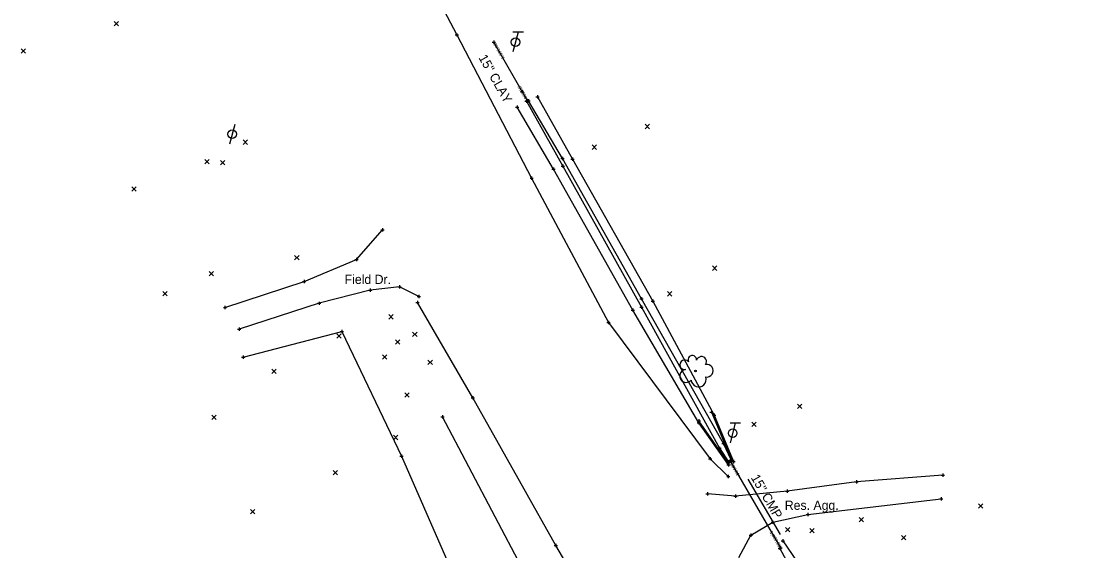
# Model space of a CAD drawing. Extents: x 2298098 to 2302860, y 557788 to 564251.
# Drawn here: x 2299909.5 to 2300233.1, y 560543.3 to 560704.7 of the extents above; entities that cross this region are included whole.
import ezdxf

# ---------------------------------------------------------------- set-up
doc = ezdxf.new("R2010")
doc.units = 0
for name, color, linetype in [('DR_X_Ditch', 7, 'Continuous'), ('DR_X_Elev_Flow', 7, 'Continuous'), ('DR_X_Storm_Sewer', 7, 'Continuous'), ('DR_X_Text', 7, 'Continuous'), ('PV_X_Curb', 7, 'Continuous'), ('PV_X_Driveway', 7, 'Continuous'), ('PV_X_Text', 7, 'Continuous'), ('SC_Scratch1', 7, 'Continuous'), ('SV_X_Break_Lines', 7, 'Continuous'), ('SV_X_Random_Point', 7, 'Continuous'), ('SV_X_Shot_Marker', 7, 'Continuous'), ('UT_X_Telecom_Cells', 7, 'Continuous'), ('UT_X_Unknown_Cells', 7, 'Continuous'), ('VG_X_Cells', 7, 'Continuous')]:
    doc.layers.add(name, color=color, linetype=linetype)

msp = doc.modelspace()

# ---------------------------------------------------------------- linework, layer by layer
at = {"layer": 'DR_X_Ditch'}
for points in [[(2300063.52, 560680.3), (2300074.62, 560660.51), (2300098.62, 560617.55), (2300122.4, 560574.49), (2300125.1, 560570.36)], [(2300125.91, 560570.98), (2300123.6, 560575.94), (2300098.62, 560620.12), (2300074.45, 560662.9), (2300064.1, 560680.42)], [(2300140.73, 560543.99), (2300148.01, 560530.6), (2300173.36, 560487.93), (2300199.8, 560447.46)]]:
    msp.add_lwpolyline(points, dxfattribs=at)
at = {"layer": 'DR_X_Elev_Flow'}
for p, q in [((2300053.09, 560698.3), (2300054.09, 560698.3)), ((2300053.59, 560698.8), (2300053.59, 560697.8)), ((2300053.59, 560698.3), (2300053.59, 560698.3)), ((2300063.29, 560680.42), (2300064.29, 560680.42)), ((2300063.79, 560680.92), (2300063.79, 560679.92)), ((2300063.79, 560680.42), (2300063.79, 560680.42)), ((2300125.63, 560571.09), (2300125.63, 560570.09)), ((2300125.13, 560570.59), (2300126.13, 560570.59)), ((2300125.63, 560570.59), (2300125.63, 560570.59)), ((2300140.45, 560544.14), (2300141.45, 560544.14)), ((2300140.95, 560544.64), (2300140.95, 560543.64)), ((2300140.95, 560544.14), (2300140.95, 560544.14))]:
    msp.add_line(p, q, dxfattribs=at)
at = {"layer": 'DR_X_Storm_Sewer'}
for p, q in [((2300063.79, 560680.42), (2300053.59, 560698.3)), ((2300125.63, 560570.59), (2300140.95, 560544.14))]:
    msp.add_line(p, q, dxfattribs=at)
at = {"layer": 'DR_X_Text'}
msp.add_line((2300140.93, 560548.2), (2300131.15, 560565.1), dxfattribs=at)
at = {"layer": 'PV_X_Curb'}
for points in [[(2300066.91, 560681.69), (2300077.5, 560662.65), (2300102.02, 560619.33), (2300120.74, 560584.58), (2300126.65, 560570.43)], [(2300125.1, 560569.46), (2300116.03, 560582.25), (2300095.96, 560616.58), (2300071.76, 560659.65), (2300060.65, 560678.51)], [(2300119.92, 560585.56), (2300126.1, 560570.69)], [(2300124.98, 560570.09), (2300116.05, 560582.88)], [(2300141.66, 560546.3), (2300150.4, 560533.52), (2300175.79, 560490.38), (2300201.81, 560451.09), (2300229.19, 560414.22)]]:
    msp.add_lwpolyline(points, dxfattribs=at)
at = {"layer": 'PV_X_Driveway'}
for points in [[(2299971.58, 560617.42), (2299995.74, 560625.32), (2300011.7, 560632.08), (2300019.59, 560641.14)], [(2300030.65, 560620.78), (2300024.79, 560623.76), (2300015.85, 560622.74), (2300000.3, 560618.7), (2299975.89, 560610.83)], [(2300190.42, 560566.32), (2300164.1, 560564.3), (2300143.01, 560561.46), (2300127.24, 560559.9), (2300118.69, 560560.61)], [(2300128.29, 560541.17), (2300131.9, 560547.98), (2300138.66, 560551.93), (2300149.28, 560554.27), (2300189.99, 560559.13)]]:
    msp.add_lwpolyline(points, dxfattribs=at)
at = {"layer": 'SV_X_Break_Lines'}
for points in [[(2299980.36, 560823), (2299996.31, 560788.88), (2300018.92, 560744.96), (2300042.25, 560700.52), (2300065.09, 560656.83), (2300088.55, 560612.83), (2300119.49, 560571.33), (2300125.05, 560565.91)], [(2300398.05, 560096.62), (2300363.97, 560133.96), (2300330.95, 560172.02), (2300298.04, 560211.71), (2300266.61, 560251.65), (2300236.37, 560291.53), (2300207.47, 560332.84), (2300178.37, 560374.68), (2300151.28, 560415.3), (2300123.6, 560459.08), (2300097.78, 560501.73), (2300072.42, 560544.84), (2300047.18, 560589.85), (2300030.27, 560619)], [(2299977.11, 560602.31), (2300007.25, 560610.14), (2300025.38, 560572.14), (2300045.56, 560526.04), (2300066.45, 560482.53), (2300086, 560434.38), (2300113.14, 560386.24), (2300137.98, 560345.34), (2300163.42, 560304.75), (2300191.32, 560264.85), (2300220.76, 560218.4), (2300248.98, 560175.76), (2300284.57, 560133.57), (2300319.56, 560088.68), (2300350.07, 560059.81)], [(2300381.27, 560083.36), (2300351.97, 560122.59), (2300319.35, 560161.59), (2300285.86, 560201.5), (2300253.42, 560241.93), (2300223.14, 560281.83), (2300192.99, 560321.43), (2300165.5, 560364.16), (2300137.47, 560403.52), (2300110, 560448.16), (2300084.4, 560491.86), (2300061.94, 560538.37), (2300037.88, 560584.07)]]:
    msp.add_lwpolyline(points, dxfattribs=at)
at = {"layer": 'SV_X_Random_Point'}
for p, q in [((2299937.78, 560703.34), (2299939.11, 560704.68)), ((2299937.78, 560704.68), (2299939.11, 560703.34)), ((2299909.45, 560694.96), (2299910.79, 560696.29)), ((2299909.45, 560696.29), (2299910.79, 560694.96)), ((2300099.67, 560671.95), (2300101.01, 560673.28)), ((2300099.67, 560673.28), (2300101.01, 560671.95)), ((2299977.1, 560667.17), (2299978.43, 560668.5)), ((2299977.1, 560668.5), (2299978.43, 560667.17)), ((2300083.51, 560665.65), (2300084.85, 560666.98)), ((2300083.51, 560666.98), (2300084.85, 560665.65)), ((2299965.46, 560661.22), (2299966.8, 560662.56)), ((2299965.46, 560662.56), (2299966.8, 560661.22)), ((2299970.23, 560660.91), (2299971.56, 560662.24)), ((2299970.23, 560662.24), (2299971.56, 560660.91)), ((2299943.13, 560652.89), (2299944.46, 560654.22)), ((2299943.13, 560654.22), (2299944.46, 560652.89)), ((2299992.82, 560631.96), (2299994.15, 560633.3)), ((2299992.82, 560633.3), (2299994.15, 560631.96)), ((2300120.21, 560628.75), (2300121.54, 560630.09)), ((2300120.21, 560630.09), (2300121.54, 560628.75)), ((2299966.72, 560627.07), (2299968.05, 560628.4)), ((2299966.72, 560628.4), (2299968.05, 560627.07)), ((2299952.61, 560621.01), (2299953.95, 560622.34)), ((2299952.61, 560622.34), (2299953.95, 560621.01)), ((2300106.47, 560620.93), (2300107.8, 560622.26)), ((2300106.47, 560622.26), (2300107.8, 560620.93)), ((2300021.53, 560613.92), (2300022.86, 560615.25)), ((2300021.53, 560615.25), (2300022.86, 560613.92)), ((2300028.8, 560608.6), (2300030.13, 560609.94)), ((2300028.8, 560609.94), (2300030.13, 560608.6)), ((2300005.64, 560608.06), (2300006.98, 560609.39)), ((2300005.64, 560609.39), (2300006.98, 560608.06)), ((2300023.54, 560606.25), (2300024.87, 560607.59)), ((2300023.54, 560607.59), (2300024.87, 560606.25)), ((2300019.57, 560601.7), (2300020.91, 560603.03)), ((2300019.57, 560603.03), (2300020.91, 560601.7)), ((2300033.47, 560600.04), (2300034.81, 560601.37)), ((2300033.47, 560601.37), (2300034.81, 560600.04)), ((2299985.88, 560597.32), (2299987.22, 560598.65)), ((2299985.88, 560598.65), (2299987.22, 560597.32)), ((2300026.44, 560590.12), (2300027.77, 560591.45)), ((2300026.44, 560591.45), (2300027.77, 560590.12)), ((2300146.15, 560586.65), (2300147.49, 560587.99)), ((2300146.15, 560587.99), (2300147.49, 560586.65)), ((2299967.59, 560583.24), (2299968.92, 560584.57)), ((2299967.59, 560584.57), (2299968.92, 560583.24)), ((2300132.19, 560581.14), (2300133.52, 560582.48)), ((2300132.19, 560582.48), (2300133.52, 560581.14)), ((2300022.99, 560577.11), (2300024.32, 560578.45)), ((2300022.99, 560578.45), (2300024.32, 560577.11)), ((2300004.52, 560566.42), (2300005.86, 560567.75)), ((2300004.52, 560567.75), (2300005.86, 560566.42)), ((2299979.39, 560554.47), (2299980.72, 560555.81)), ((2299979.39, 560555.81), (2299980.72, 560554.47)), ((2300201.29, 560556.26), (2300202.62, 560557.6)), ((2300201.29, 560557.6), (2300202.62, 560556.26)), ((2300164.94, 560552.08), (2300166.27, 560553.42)), ((2300164.94, 560553.42), (2300166.27, 560552.08)), ((2300142.48, 560549.05), (2300143.81, 560550.38)), ((2300142.48, 560550.38), (2300143.81, 560549.05)), ((2300149.92, 560548.73), (2300151.25, 560550.06)), ((2300149.92, 560550.06), (2300151.25, 560548.73)), ((2300177.81, 560546.62), (2300179.14, 560547.95)), ((2300177.81, 560547.95), (2300179.14, 560546.62))]:
    msp.add_line(p, q, dxfattribs=at)
at = {"layer": 'SV_X_Shot_Marker'}
for p, q in [((2300042.25, 560701.02), (2300042.25, 560700.02)), ((2300041.75, 560700.52), (2300042.75, 560700.52)), ((2300042.25, 560700.52), (2300042.25, 560700.52)), ((2300061.68, 560683.23), (2300062.68, 560683.23)), ((2300062.18, 560683.73), (2300062.18, 560682.73)), ((2300062.18, 560683.23), (2300062.18, 560683.23)), ((2300066.41, 560681.69), (2300067.41, 560681.69)), ((2300066.91, 560682.19), (2300066.91, 560681.19)), ((2300066.91, 560681.69), (2300066.91, 560681.69)), ((2300060.15, 560678.51), (2300061.15, 560678.51)), ((2300060.65, 560679.01), (2300060.65, 560678.01)), ((2300060.65, 560678.51), (2300060.65, 560678.51)), ((2300063.02, 560680.3), (2300064.02, 560680.3)), ((2300063.52, 560680.8), (2300063.52, 560679.8)), ((2300063.52, 560680.3), (2300063.52, 560680.3)), ((2300063.6, 560680.42), (2300064.6, 560680.42)), ((2300064.1, 560680.92), (2300064.1, 560679.92)), ((2300064.1, 560680.42), (2300064.1, 560680.42)), ((2300073.95, 560662.9), (2300074.95, 560662.9)), ((2300074.45, 560663.4), (2300074.45, 560662.4)), ((2300074.45, 560662.9), (2300074.45, 560662.9)), ((2300077, 560662.65), (2300078, 560662.65)), ((2300077.5, 560663.15), (2300077.5, 560662.15)), ((2300077.5, 560662.65), (2300077.5, 560662.65)), ((2300071.26, 560659.65), (2300072.26, 560659.65)), ((2300071.76, 560660.15), (2300071.76, 560659.15)), ((2300071.76, 560659.65), (2300071.76, 560659.65)), ((2300074.12, 560660.51), (2300075.12, 560660.51)), ((2300074.62, 560661.01), (2300074.62, 560660.01)), ((2300074.62, 560660.51), (2300074.62, 560660.51)), ((2300064.59, 560656.83), (2300065.59, 560656.83)), ((2300065.09, 560657.33), (2300065.09, 560656.33)), ((2300065.09, 560656.83), (2300065.09, 560656.83)), ((2300019.09, 560641.14), (2300020.09, 560641.14)), ((2300019.59, 560641.64), (2300019.59, 560640.64)), ((2300019.59, 560641.14), (2300019.59, 560641.14)), ((2300011.7, 560632.58), (2300011.7, 560631.58)), ((2300011.2, 560632.08), (2300012.2, 560632.08)), ((2300011.7, 560632.08), (2300011.7, 560632.08)), ((2299995.24, 560625.32), (2299996.24, 560625.32)), ((2299995.74, 560625.82), (2299995.74, 560624.82)), ((2299995.74, 560625.32), (2299995.74, 560625.32)), ((2300015.85, 560623.24), (2300015.85, 560622.24)), ((2300024.29, 560623.76), (2300025.29, 560623.76)), ((2300024.79, 560624.26), (2300024.79, 560623.26)), ((2300024.79, 560623.76), (2300024.79, 560623.76)), ((2300015.35, 560622.74), (2300016.35, 560622.74)), ((2300015.85, 560622.74), (2300015.85, 560622.74)), ((2300030.15, 560620.78), (2300031.15, 560620.78)), ((2300030.65, 560621.28), (2300030.65, 560620.28)), ((2300030.65, 560620.78), (2300030.65, 560620.78)), ((2300098.12, 560620.12), (2300099.12, 560620.12)), ((2300098.62, 560620.62), (2300098.62, 560619.62)), ((2300098.62, 560620.12), (2300098.62, 560620.12)), ((2300102.02, 560619.83), (2300102.02, 560618.83)), ((2299971.08, 560617.42), (2299972.08, 560617.42)), ((2299971.58, 560617.92), (2299971.58, 560616.92)), ((2299971.58, 560617.42), (2299971.58, 560617.42)), ((2299999.8, 560618.7), (2300000.8, 560618.7)), ((2300000.3, 560619.2), (2300000.3, 560618.2)), ((2300000.3, 560618.7), (2300000.3, 560618.7)), ((2300029.77, 560619), (2300030.77, 560619)), ((2300030.27, 560619.5), (2300030.27, 560618.5)), ((2300030.27, 560619), (2300030.27, 560619)), ((2300095.46, 560616.58), (2300096.46, 560616.58)), ((2300095.96, 560617.08), (2300095.96, 560616.08)), ((2300095.96, 560616.58), (2300095.96, 560616.58)), ((2300098.12, 560617.55), (2300099.12, 560617.55)), ((2300098.62, 560618.05), (2300098.62, 560617.05)), ((2300098.62, 560617.55), (2300098.62, 560617.55)), ((2300101.52, 560619.33), (2300102.52, 560619.33)), ((2300102.02, 560619.33), (2300102.02, 560619.33)), ((2300088.55, 560613.33), (2300088.55, 560612.33)), ((2299975.39, 560610.83), (2299976.39, 560610.83)), ((2299975.89, 560611.33), (2299975.89, 560610.33)), ((2299975.89, 560610.83), (2299975.89, 560610.83)), ((2300006.75, 560610.14), (2300007.75, 560610.14)), ((2300007.25, 560610.64), (2300007.25, 560609.64)), ((2300007.25, 560610.14), (2300007.25, 560610.14)), ((2300088.05, 560612.83), (2300089.05, 560612.83)), ((2300088.55, 560612.83), (2300088.55, 560612.83)), ((2299976.61, 560602.31), (2299977.61, 560602.31)), ((2299977.11, 560602.81), (2299977.11, 560601.81)), ((2299977.11, 560602.31), (2299977.11, 560602.31)), ((2300046.68, 560589.85), (2300047.68, 560589.85)), ((2300047.18, 560590.35), (2300047.18, 560589.35)), ((2300047.18, 560589.85), (2300047.18, 560589.85)), ((2300037.38, 560584.07), (2300038.38, 560584.07)), ((2300037.88, 560584.57), (2300037.88, 560583.57)), ((2300037.88, 560584.07), (2300037.88, 560584.07)), ((2300119.42, 560585.56), (2300120.42, 560585.56)), ((2300119.92, 560586.06), (2300119.92, 560585.06)), ((2300119.92, 560585.56), (2300119.92, 560585.56)), ((2300120.24, 560584.58), (2300121.24, 560584.58)), ((2300120.74, 560585.08), (2300120.74, 560584.08)), ((2300120.74, 560584.58), (2300120.74, 560584.58)), ((2300115.53, 560582.25), (2300116.53, 560582.25)), ((2300115.55, 560582.88), (2300116.55, 560582.88)), ((2300116.03, 560582.75), (2300116.03, 560581.75)), ((2300116.03, 560582.25), (2300116.03, 560582.25)), ((2300116.05, 560583.38), (2300116.05, 560582.38)), ((2300116.05, 560582.88), (2300116.05, 560582.88)), ((2300121.9, 560574.49), (2300122.9, 560574.49)), ((2300122.4, 560574.99), (2300122.4, 560573.99)), ((2300122.4, 560574.49), (2300122.4, 560574.49)), ((2300123.1, 560575.94), (2300124.1, 560575.94)), ((2300123.6, 560576.44), (2300123.6, 560575.44)), ((2300123.6, 560575.94), (2300123.6, 560575.94)), ((2300024.88, 560572.14), (2300025.88, 560572.14)), ((2300025.38, 560572.64), (2300025.38, 560571.64)), ((2300025.38, 560572.14), (2300025.38, 560572.14)), ((2300118.99, 560571.33), (2300119.99, 560571.33)), ((2300119.49, 560571.83), (2300119.49, 560570.83)), ((2300119.49, 560571.33), (2300119.49, 560571.33)), ((2300125.91, 560571.48), (2300125.91, 560570.48)), ((2300126.1, 560571.19), (2300126.1, 560570.19)), ((2300124.48, 560570.09), (2300125.48, 560570.09)), ((2300124.6, 560570.36), (2300125.6, 560570.36)), ((2300124.6, 560569.46), (2300125.6, 560569.46)), ((2300124.98, 560570.59), (2300124.98, 560569.59)), ((2300124.98, 560570.09), (2300124.98, 560570.09)), ((2300125.1, 560570.86), (2300125.1, 560569.86)), ((2300125.1, 560570.36), (2300125.1, 560570.36)), ((2300125.1, 560569.96), (2300125.1, 560568.96)), ((2300125.1, 560569.46), (2300125.1, 560569.46)), ((2300125.41, 560570.98), (2300126.41, 560570.98)), ((2300125.6, 560570.69), (2300126.6, 560570.69)), ((2300125.91, 560570.98), (2300125.91, 560570.98)), ((2300126.1, 560570.69), (2300126.1, 560570.69)), ((2300126.15, 560570.43), (2300127.15, 560570.43)), ((2300126.65, 560570.93), (2300126.65, 560569.93)), ((2300126.65, 560570.43), (2300126.65, 560570.43)), ((2300124.55, 560565.91), (2300125.55, 560565.91)), ((2300125.05, 560566.41), (2300125.05, 560565.41)), ((2300125.05, 560565.91), (2300125.05, 560565.91)), ((2300164.1, 560564.8), (2300164.1, 560563.8)), ((2300189.92, 560566.32), (2300190.92, 560566.32)), ((2300190.42, 560566.82), (2300190.42, 560565.82)), ((2300190.42, 560566.32), (2300190.42, 560566.32)), ((2300142.51, 560561.46), (2300143.51, 560561.46)), ((2300143.01, 560561.96), (2300143.01, 560560.96)), ((2300143.01, 560561.46), (2300143.01, 560561.46)), ((2300163.6, 560564.3), (2300164.6, 560564.3)), ((2300164.1, 560564.3), (2300164.1, 560564.3)), ((2300118.19, 560560.61), (2300119.19, 560560.61)), ((2300118.69, 560561.11), (2300118.69, 560560.11)), ((2300118.69, 560560.61), (2300118.69, 560560.61)), ((2300126.74, 560559.9), (2300127.74, 560559.9)), ((2300127.24, 560560.4), (2300127.24, 560559.4)), ((2300127.24, 560559.9), (2300127.24, 560559.9)), ((2300189.49, 560559.13), (2300190.49, 560559.13)), ((2300189.99, 560559.63), (2300189.99, 560558.63)), ((2300189.99, 560559.13), (2300189.99, 560559.13)), ((2300138.16, 560551.93), (2300139.16, 560551.93)), ((2300138.66, 560552.43), (2300138.66, 560551.43)), ((2300138.66, 560551.93), (2300138.66, 560551.93)), ((2300148.78, 560554.27), (2300149.78, 560554.27)), ((2300149.28, 560554.77), (2300149.28, 560553.77)), ((2300149.28, 560554.27), (2300149.28, 560554.27)), ((2300131.9, 560548.48), (2300131.9, 560547.48)), ((2300072.42, 560545.34), (2300072.42, 560544.34)), ((2300131.4, 560547.98), (2300132.4, 560547.98)), ((2300131.9, 560547.98), (2300131.9, 560547.98)), ((2300141.16, 560546.3), (2300142.16, 560546.3)), ((2300141.66, 560546.8), (2300141.66, 560545.8)), ((2300141.66, 560546.3), (2300141.66, 560546.3)), ((2300071.92, 560544.84), (2300072.92, 560544.84)), ((2300072.42, 560544.84), (2300072.42, 560544.84)), ((2300140.23, 560543.99), (2300141.23, 560543.99)), ((2300140.73, 560544.49), (2300140.73, 560543.49)), ((2300140.73, 560543.99), (2300140.73, 560543.99))]:
    msp.add_line(p, q, dxfattribs=at)
at = {"layer": 'UT_X_Telecom_Cells'}
for p, q in [((2300060.95, 560701.35), (2300059.34, 560695.35)), ((2300062.55, 560701.35), (2300059.35, 560701.35)), ((2300127.18, 560582.13), (2300125.57, 560576.13)), ((2300128.78, 560582.13), (2300125.58, 560582.13))]:
    msp.add_line(p, q, dxfattribs=at)
for centre in [(2300060.14, 560698.35), (2300126.38, 560579.13)]:
    msp.add_circle(centre, 1.3, dxfattribs=at)
at = {"layer": 'UT_X_Unknown_Cells'}
msp.add_line((2299974.56, 560673.27), (2299972.95, 560667.27), dxfattribs=at)
msp.add_circle((2299973.76, 560670.27), 1.3, dxfattribs=at)
at = {"layer": 'VG_X_Cells'}
msp.add_circle((2300115.05, 560598.09), 0.24, dxfattribs=at)
for centre, radius, start, end in [((2300111.75, 560599.96), 1.47, 39.0625, 279.5412), ((2300114.07, 560601.46), 1.32, 354.0047, 205.9741), ((2300116.88, 560600.92), 1.55, 323.83, 165.0376), ((2300112.2, 560596.54), 1.97, 96.1722, 320.5737), ((2300118.52, 560598.13), 1.91, 259.1453, 101.4596), ((2300116, 560595.49), 2.28, 184.9476, 19.4572)]:
    msp.add_arc(centre, radius, start, end, dxfattribs=at)

# ---------------------------------------------------------------- texts
at = {"layer": 'DR_X_Text'}
for s, rotation, p in [('15" CLAY', 299.6889, (2300048.8, 560693.61)), ('15" CMP', 300.0722, (2300131.84, 560565.56))]:
    msp.add_text(s, height=2.8, rotation=rotation, dxfattribs=at).set_placement(p)
at = {"layer": 'PV_X_Text'}
for s, p in [('Field Dr.', (2300008.06, 560624.61)), ('Res. Agg.', (2300142.27, 560555.73))]:
    msp.add_text(s, height=2.8, dxfattribs=at).set_placement(p)
at = {"layer": 'SC_Scratch1'}
for s, rotation, p in [("1,096.03'", 119.6889, (2300056.9, 560693.51)), ("1096.03'", 119.6889, (2300064.22, 560680.67)), ("1089.31'", 300.0722, (2300125.2, 560570.34)), ("1,087.60'", 300.0722, (2300137.61, 560548.9))]:
    msp.add_text(s, height=1, rotation=rotation, dxfattribs=at).set_placement(p)

doc.saveas('drawing.dxf')
